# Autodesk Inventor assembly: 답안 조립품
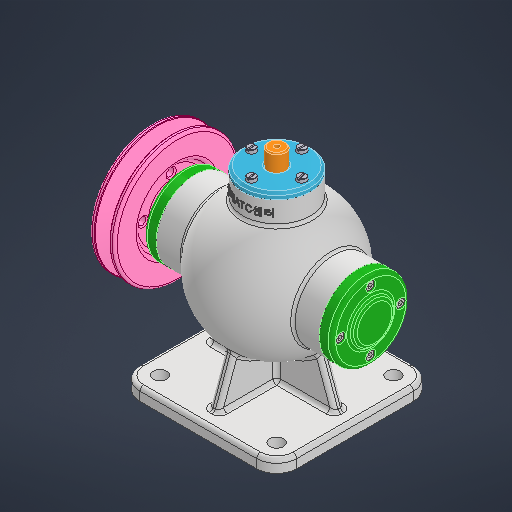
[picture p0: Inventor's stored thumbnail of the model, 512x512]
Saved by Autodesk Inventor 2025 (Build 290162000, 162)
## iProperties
Created: 2025-08
Part Number: 답안 조립품
Document SubType Name: Assembly
Designer: infra14
Author: infra14
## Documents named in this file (15)
- C:\Users\infra14\Desktop\750807V1005\답안 조립품.iam
- C:\Users\infra14\Desktop\750807V1005\본체.ipt
- C:\Users\infra14\Desktop\750807V1005\V-벨트풀리\V-벨트풀리.ipt
- C:\Users\infra14\Desktop\750807V1005\너트 M8\너트 M8.ipt
- C:\Users\infra14\Desktop\750807V1005\뒤커버\뒤커버.ipt
- C:\Users\infra14\Desktop\750807V1005\베어링- 6202\베어링- 6202.ipt
- C:\Users\infra14\Desktop\750807V1005\볼트 M4 x 12\볼트 M4 x 12.ipt
- C:\Users\infra14\Desktop\750807V1005\볼트 M4 x 16\볼트 M4 x 16.ipt
- C:\Users\infra14\Desktop\750807V1005\상부커버\상부커버.ipt
- C:\Users\infra14\Desktop\750807V1005\슬라이드\슬라이드.ipt
- C:\Users\infra14\Desktop\750807V1005\앞커버\앞커버.ipt
- C:\Users\infra14\Desktop\750807V1005\오일실 15 30 7\오일실 15 30 7.ipt
- C:\Users\infra14\Desktop\750807V1005\칼라\칼라.ipt
- C:\Users\infra14\Desktop\750807V1005\키 4 x 4 x 12\키 4 x 4 x 12.ipt
- C:\Users\infra14\Desktop\750807V1005\편심축\편심축.ipt
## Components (1 placed, 1 different names)
1. V-벨트풀리:1
